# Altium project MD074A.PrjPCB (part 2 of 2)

## Sheet MD074A.SchDoc
size 431 x 279 mm; Date: Not shown in title block; ApprovedBy: Not shown in title block; CheckedBy: Not shown in title block; Author: Not shown in title block; CompanyName: Not shown in title block; Engineer: Not shown in title block; Organization: Not shown in title block; Address1: Not shown in title block; Address2: Not shown in title block; Address3: Not shown in title block; Address4: Not shown in title block; DocumentNumber: 2; Revision: Use project parameter SCH_Rev; SheetNumber: 2; SheetTotal: 3; PageSetup: Record=PageOptions¦CenterHorizontal=True¦CenterVertical=True¦PrintScale=1.00¦XCorrection=1.00¦YCorrection=1.00¦PrintKind=0¦BorderSize=5000000¦LeftOffset=0¦BottomOffset=0¦Orientation=2¦PaperLength=1000¦PaperWidth=1000¦Scale=100¦PaperSource=15¦PrintQuality=600¦MediaType=1¦DitherType=10¦PaperKind=Letter¦PrintScaleMode=1
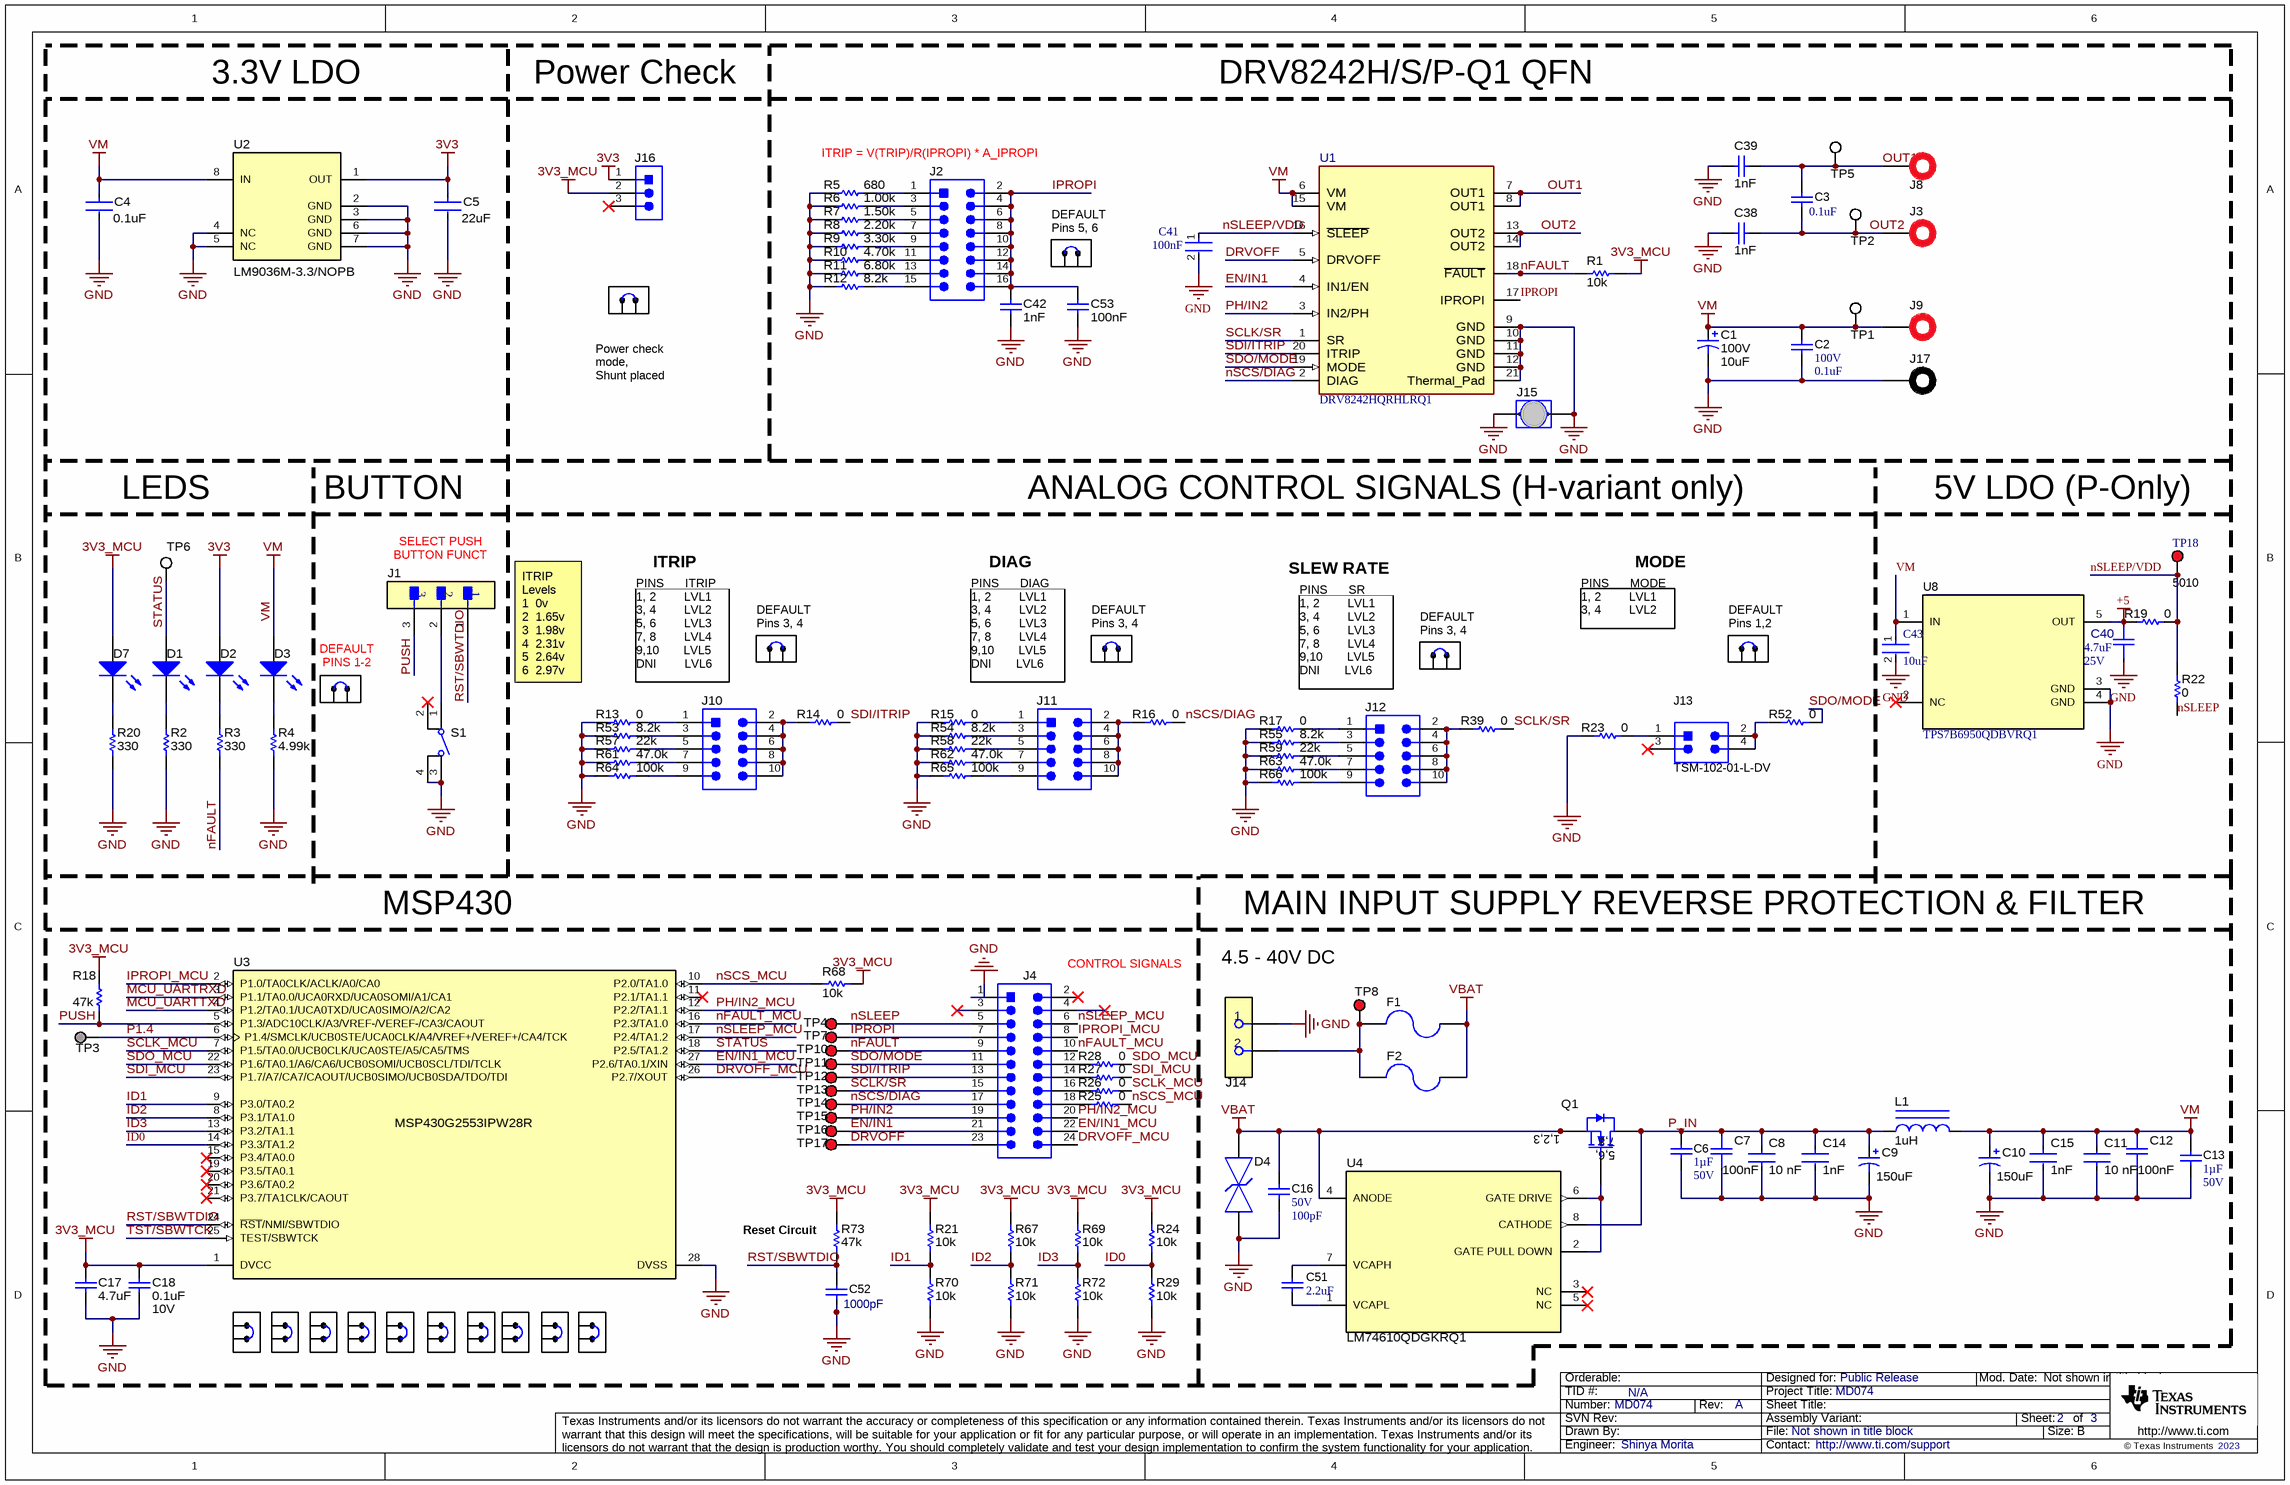
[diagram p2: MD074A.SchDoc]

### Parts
C1  VDC_V: 100V  ValueDisplayed: 10uF  [SM_RADIAL_E]  (hidden comment: EEE-2AA100UP)
C2  VDC_V: 100V  ValueDisplayed: 0.1uF  [1206_180]  (hidden comment: C3216X7R2A104K160AA)
C3  ValueDisplayed: 0.1uF  [1206_180]  (hidden comment: C3216X7R2A104K160AA)
C4  value 0.1uF  [FP-CL10-0_1-MFG]  (hidden comment: CL10B104JB8NNNC)
C5  value 22uF  [FP-CL10-IPC_A]  (hidden comment: CL10A226MQ8NUNE)
C6  Cap_F: 1µF  VDC_V: 50V  [0805_HV]  (hidden comment: 885012207103)
C7  Cap_F: 100nF  [FP-885012206095_0603-MFG]  (hidden comment: 885012206095)
C8  value 10 nF  [FP-CC0603-DA-MFG]  (hidden comment: CC0603KPX7R9BB103)
C9  ValueDisplayed: 150uF  [SM_RADIAL_G]  (hidden comment: EEE-FK1H151P)
C10  ValueDisplayed: 150uF  [SM_RADIAL_G]  (hidden comment: EEE-FK1H151P)
C11  value 10 nF  [FP-CC0603-DA-MFG]  (hidden comment: CC0603KPX7R9BB103)
C12  Cap_F: 100nF  [FP-885012206095_0603-MFG]  (hidden comment: 885012206095)
C13  Cap_F: 1µF  VDC_V: 50V  [0805_HV]  (hidden comment: 885012207103)
C14  1nF  [FP-C0603C-CF-MFG]
C15  1nF  [FP-C0603C-CF-MFG]
C16  VDC_V: 50V  ValueDisplayed: 100pF  [0805_HV]  (hidden comment: 885012007057)
C17  ValueDisplayed: 4.7uF  [0402_065L]  (hidden comment: Capacitor)
C18  ValueDisplayed: 0.1uF  VDC_V: 10V  [0603L]  (hidden comment: 885012206020)
C38  Cap_F: 1nF  [0603]  (hidden comment: CGA3E2X7R2A102K080AA)
C39  Cap_F: 1nF  [0603]  (hidden comment: CGA3E2X7R2A102K080AA)
C40  ValueDisplayed: 4.7uF  VDC_V: 25V  [FP-GRM188R61E475KE15D_0603-MFG]  (hidden comment: GRM188R61E475KE15D)
C41  Capacitance: 100nF  [FP-CGA3E-0_3-0_1-MFG]  (hidden comment: CGA3E2X7R1E104K080AA)
C42  Cap_F: 1nF  [0603]  (hidden comment: CGA3E2X7R2A102K080AA)
C43  Capacitance: 10uF  [FP-C5750-230-0_5-MFG]  (hidden comment: C5750X7S2A106M230KE)
C51  ValueDisplayed: 2.2uF  [0805_HV]  (hidden comment: C2012X5R1H225K125AB)
C52  ValueDisplayed: 1000pF  [0402]  (hidden comment: GRM155R71H102KA01D)
C53  Cap_F: 100nF  [0603]  (hidden comment: CGA3E2X7R1H104K080AA)
D1  150080VS75000  [0805_A]  (value not drawn)
D2  150080SS75000  [0805_A]  (value not drawn)
D3  150080VS75000  [0805_A]  (value not drawn)
D4  SMAJ36CA  [FP-SMAJ-CA-MFG]  (value not drawn)
D7  150080VS75000  [0805_A]  (value not drawn)
F1  0463015.ER  [Fuse_0463]  (value not drawn)
F2  0463030.ER  [Fuse_0463]  (value not drawn)
J1  PR20203VBNN  [FP-PR20203VBNN-MFG]  (value not drawn)
J2  TSM-108-01-L-DV  [Samtec_TSM-108-01-x-DV]  (value not drawn)
J3  CT3151SP-2  [CTE_CT3151SP-2]  (value not drawn)
J4  67997-224HLF  [FCI_67997-224HLF]  (value not drawn)
J8  CT3151SP-2  [CTE_CT3151SP-2]  (value not drawn)
J9  CT3151SP-2  [CTE_CT3151SP-2]  (value not drawn)
J10  TSM-105-01-L-DV-P  [Samtec_TSM-105-01-x-DV]  (value not drawn)
J11  TSM-105-01-L-DV-P  [Samtec_TSM-105-01-x-DV]  (value not drawn)
J12  TSM-105-01-L-DV-P  [Samtec_TSM-105-01-x-DV]  (value not drawn)
J13  TSM-102-01-L-DV  [Samtec_TSM-102-01-x-DV]
J14  691256610002  [FP-691256610002_HDR2-MFG]  (value not drawn)
J15  D3082-05  [Harwin_D3082-05]  (value not drawn)
J16  TSW-103-08-G-S  [Samtec_TSW-103-08-x-S]  (value not drawn)
J17  CT3151SP-0  [CTE_CT3151SP-0]  (value not drawn)
L1  ValueDisplayed: 1uH  [WE-HCC_1210]  (hidden comment: 7443320100)
Q1  CSD18513Q5A  [DQJ0008A]  (value not drawn)
R1  ValueDisplayed: 10k  [0603]  (hidden comment: RC0603JR-0710KL)
R2  ValueDisplayed: 330  [0603L]  (hidden comment: CMP-0025785-4)
R3  ValueDisplayed: 330  [0603L]  (hidden comment: CMP-0025785-4)
R4  ValueDisplayed: 4.99k  [0603L]  (hidden comment: CRCW06034K99FKEAC)
R5  ValueDisplayed: 680  [0603]  (hidden comment: RC0603FR-07680RL)
R6  ValueDisplayed: 1.00k  [0603]  (hidden comment: RC0603FR-071KL)
R7  ValueDisplayed: 1.50k  [0603]  (hidden comment: RC0603FR-071K5L)
R8  ValueDisplayed: 2.20k  [0603]  (hidden comment: RC0603FR-072K2L)
R9  ValueDisplayed: 3.30k  [0603]  (hidden comment: RC0603FR-073K3L)
R10  ValueDisplayed: 4.70k  [0603]  (hidden comment: RC0603FR-074K7L)
R11  ValueDisplayed: 6.80k  [0603]  (hidden comment: RC0603FR-076K8L)
R12  ValueDisplayed: 8.2k  [0603]  (hidden comment: CRCW06038K20JNEA)
R13  ValueDisplayed: 0  [0603]  (hidden comment: PMR03EZPJ000)
R14  ValueDisplayed: 0  [0603]  (hidden comment: PMR03EZPJ000)
R15  ValueDisplayed: 0  [0603]  (hidden comment: PMR03EZPJ000)
R16  ValueDisplayed: 0  [0603]  (hidden comment: PMR03EZPJ000)
R17  ValueDisplayed: 0  [0603]  (hidden comment: PMR03EZPJ000)
R18  ValueDisplayed: 47k  [0603]  (hidden comment: RC0603JR-0747KL)
R19  ValueDisplayed: 0  [0603]  (hidden comment: PMR03EZPJ000)
R20  ValueDisplayed: 330  [0603L]  (hidden comment: CMP-0025785-4)
R21  ValueDisplayed: 10k  [0603]  (hidden comment: RC0603JR-0710KL)
R22  ValueDisplayed: 0  [0603]  (hidden comment: PMR03EZPJ000)
R23  ValueDisplayed: 0  [0603]  (hidden comment: PMR03EZPJ000)
R24  ValueDisplayed: 10k  [0603]  (hidden comment: RC0603JR-0710KL)
R25  value 0  [RESC1609X55X30NL10T20]  (hidden comment: CRCW06030000Z0EAHP)
R26  value 0  [RESC1609X55X30NL10T20]  (hidden comment: CRCW06030000Z0EAHP)
R27  value 0  [RESC1609X55X30NL10T20]  (hidden comment: CRCW06030000Z0EAHP)
R28  value 0  [RESC1609X55X30NL10T20]  (hidden comment: CRCW06030000Z0EAHP)
R29  ValueDisplayed: 10k  [0603]  (hidden comment: RC0603JR-0710KL)
R39  ValueDisplayed: 0  [0603]  (hidden comment: PMR03EZPJ000)
R52  ValueDisplayed: 0  [0603]  (hidden comment: PMR03EZPJ000)
R53  ValueDisplayed: 8.2k  [0603]  (hidden comment: CRCW06038K20JNEA)
R54  ValueDisplayed: 8.2k  [0603]  (hidden comment: CRCW06038K20JNEA)
R55  ValueDisplayed: 8.2k  [0603]  (hidden comment: CRCW06038K20JNEA)
R57  ValueDisplayed: 22k  [0603]  (hidden comment: CRCW060322K0JNEA)
R58  ValueDisplayed: 22k  [0603]  (hidden comment: CRCW060322K0JNEA)
R59  ValueDisplayed: 22k  [0603]  (hidden comment: CRCW060322K0JNEA)
R61  ValueDisplayed: 47.0k  [0603]  (hidden comment: CRCW060347K0FKEA)
R62  ValueDisplayed: 47.0k  [0603]  (hidden comment: CRCW060347K0FKEA)
R63  ValueDisplayed: 47.0k  [0603]  (hidden comment: CRCW060347K0FKEA)
R64  ValueDisplayed: 100k  [0603]  (hidden comment: CRCW0603100KDHEAP)
R65  ValueDisplayed: 100k  [0603]  (hidden comment: CRCW0603100KDHEAP)
R66  ValueDisplayed: 100k  [0603]  (hidden comment: CRCW0603100KDHEAP)
R67  ValueDisplayed: 10k  [0603]  (hidden comment: RC0603JR-0710KL)
R68  ValueDisplayed: 10k  [0603]  (hidden comment: RC0603JR-0710KL)
R69  ValueDisplayed: 10k  [0603]  (hidden comment: RC0603JR-0710KL)
R70  ValueDisplayed: 10k  [0603]  (hidden comment: RC0603JR-0710KL)
R71  ValueDisplayed: 10k  [0603]  (hidden comment: RC0603JR-0710KL)
R72  ValueDisplayed: 10k  [0603]  (hidden comment: RC0603JR-0710KL)
R73  ValueDisplayed: 47k  [0402]  (hidden comment: CRCW040247K0JNED)
S1  FSM4JSMA  [SW_FSM4JSMA]  (value not drawn)
SH-J1  60900213421  [Wurth_60900213421]  (value not drawn)
SH-J2  60900213421  [Wurth_60900213421]  (value not drawn)
SH-J3  60900213421  [Wurth_60900213421]  (value not drawn)
SH-J4  60900213421  [Wurth_60900213421]  (value not drawn)
SH-J5  60900213421  [Wurth_60900213421]  (value not drawn)
SH-J6  60900213421  [Wurth_60900213421]  (value not drawn)
SH-J7  60900213421  [Wurth_60900213421]  (value not drawn)
SH-J8  60900213421  [Wurth_60900213421]  (value not drawn)
SH-J9  60900213421  [Wurth_60900213421]  (value not drawn)
SH-J10  60900213421  [Wurth_60900213421]  (value not drawn)
SH-J11  60900213421  [Wurth_60900213421]  (value not drawn)
SH-J12  60900213421  [Wurth_60900213421]  (value not drawn)
SH-J13  60900213421  [Wurth_60900213421]  (value not drawn)
SH-J14  60900213421  [Wurth_60900213421]  (value not drawn)
SH-J15  60900213421  [Wurth_60900213421]  (value not drawn)
SH-J16  60900213421  [Wurth_60900213421]  (value not drawn)
SH-J17  60900213421  [Wurth_60900213421]  (value not drawn)
TP1  5015  [Testpoint_Keystone_Miniature]  (value not drawn)
TP2  5015  [Testpoint_Keystone_Miniature]  (value not drawn)
TP3  TP_H0.45P0.75  [TP_H045P075]  (value not drawn)  (no BOM)
TP4  5010  [Keystone5010]  (value not drawn)
TP5  5015  [Testpoint_Keystone_Miniature]  (value not drawn)
TP6  5015  [Testpoint_Keystone_Miniature]  (value not drawn)
TP7  5010  [Keystone5010]  (value not drawn)
TP8  5010  [Keystone5010]  (value not drawn)
TP10  5010  [Keystone5010]  (value not drawn)
TP11  5010  [Keystone5010]  (value not drawn)
TP12  5010  [Keystone5010]  (value not drawn)
TP13  5010  [Keystone5010]  (value not drawn)
TP14  5010  [Keystone5010]  (value not drawn)
TP15  5010  [Keystone5010]  (value not drawn)
TP16  5010  [Keystone5010]  (value not drawn)
TP17  5010  [Keystone5010]  (value not drawn)
TP18  5010  [Keystone5010]
U1  DRV8242HQRHLRQ1  [RHL0020B-MFG]
U2  LM9036M-3.3/NOPB  [D0008A_N]
U3  MSP430G2553IPW28R  [PW0028A_N]
U4  LM74610QDGKRQ1  [DGK0008A_N]
U8  TPS7B6950QDBVRQ1  [DBV0005A_N]

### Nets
3V3: C5.1 D2.2(A) J16.1 U2.1(OUT)
3V3_MCU: C17.1 C18.1 D7.2(A) J16.2 R1.2 R18.2 R21.1 R24.1 R67.1 R68.1 R69.1 R73.2 U3.1(DVCC)
+5: C40.2 R19.2 U8.5(OUT)
GND: C1.2(-) C2.2 C4.2 C5.2 C6.1 C7.1 C8.1 C9.2(-) C10.2(-) C11.1 C12.1 C13.1 C14.2 C15.2 C16.2 C17.2 C18.2 C38.1 C39.1 C40.1 C41.2 C42.1 C43.2 C52.2 C53.2 D4.1 J4.1 J14.1 J15.1 J15.2 J17.1 R2.1 R4.1 R5.1 R6.1 R7.1 R8.1 R9.1 R10.1 R11.1 R12.1 R13.2 R15.2 R17.2 R20.1 R23.2 R29.2 R53.1 R54.1 R55.1 R57.1 R58.1 R59.1 R61.1 R62.1 R63.1 R64.1 R65.1 R66.1 R70.2 R71.2 R72.2 S1.3 S1.4 U1.9(GND) U1.10(GND) U1.11(GND) U1.12(GND) U1.21(Thermal_Pad) U2.2(GND) U2.3(GND) U2.4(NC) U2.5(NC) U2.6(GND) U2.7(GND) U3.28(DVSS) U8.3(GND) U8.4(GND)
VBAT: C16.1 D4.2 F1.1 F2.1 Q1.1(S) Q1.2(S) Q1.3(S) U4.4(ANODE)
VM: C1.1(+) C2.1 C4.1 C10.1(+) C11.2 C12.2 C13.2 C15.1 C43.1 D3.2(A) J9.1 L1.2 TP1.1 U1.6(VM) U1.15(VM) U2.8(IN) U8.1(IN)
DRVOFF: J4.23 TP17.1 U1.5(DRVOFF)
DRVOFF_MCU: J4.24 U3.26(P2.7/XOUT)
EN/IN1: J4.21 TP16.1 U1.4(IN1/EN)
EN/IN1_MCU: J4.22 U3.27(P2.6/TA0.1/XIN)
ID0: R24.2 R29.1 U3.14(P3.3/TA1.2)
ID1: R21.2 R70.1 U3.9(P3.0/TA0.2)
ID2: R67.2 R71.1 U3.8(P3.1/TA1.0)
ID3: R69.2 R72.1 U3.13(P3.2/TA1.1)
IPROPI: C42.2 C53.1 J2.2 J2.4 J2.6 J2.8 J2.10 J2.12 J2.14 J2.16 J4.7 TP7.1 U1.17(IPROPI)
IPROPI_MCU: J4.8 U3.2(P1.0/TA0CLK/ACLK/A0/CA0)
MCU_UARTRXD: U3.3(P1.1/TA0.0/UCA0RXD/UCA0SOMI/A1/CA1)
MCU_UARTTXD: U3.4(P1.2/TA0.1/UCA0TXD/UCA0SIMO/A2/CA2)
nFAULT: J4.9 R1.1 R3.1 TP10.1 U1.18(~{FAULT})
nFAULT_MCU: J4.10 U3.16(P2.3/TA1.0)
nSCS/DIAG: J4.17 R16.1 TP14.1 U1.2(DIAG)
nSCS_MCU: R25.2 R68.2 U3.10(P2.0/TA1.0)
nSLEEP: J4.5 R22.2 TP4.1
nSLEEP/VDD: C41.1 R19.1 R22.1 TP18.1 U1.16(~{SLEEP})
nSLEEP_MCU: J4.6 U3.17(P2.4/TA1.2)
OUT1: C3.1 C39.2 J8.1 TP5.1 U1.7(OUT1) U1.8(OUT1)
OUT2: C3.2 C38.2 J3.1 TP2.1 U1.13(OUT2) U1.14(OUT2)
P1.4: TP3.1 U3.6(P1.4/SMCLK/UCB0STE/UCA0CLK/A4/VREF+/VEREF+/CA4/TCK)
P_IN: C6.2 C7.2 C8.2 C9.1(+) C14.1 L1.1 Q1.5(D) Q1.6(D) Q1.7(D) Q1.8(D) Q1.9(D) U4.8(CATHODE)
PH/IN2: J4.19 TP15.1 U1.3(IN2/PH)
PH/IN2_MCU: J4.20 U3.12(P2.2/TA1.1)
PUSH: J1.3 R18.1 U3.5(P1.3/ADC10CLK/A3/VREF-/VEREF-/CA3/CAOUT)
RST/SBWTDIO: C52.1 J1.1 R73.1 U3.24(~{RST}/NMI/SBWTDIO)
SCLK/SR: J4.15 R39.1 TP13.1 U1.1(SR)
SCLK_MCU: R26.2 U3.7(P1.5/TA0.0/UCB0CLK/UCA0STE/A5/CA5/TMS)
SDI/ITRIP: J4.13 R14.1 TP12.1 U1.20(ITRIP)
SDI_MCU: R27.2 U3.23(P1.7/A7/CA7/CAOUT/UCB0SIMO/UCB0SDA/TDO/TDI)
SDO/MODE: J4.11 R52.1 TP11.1 U1.19(MODE)
SDO_MCU: R28.2 U3.22(P1.6/TA0.1/A6/CA6/UCB0SOMI/UCB0SCL/TDI/TCLK)
STATUS: D1.2(A) TP6.1 U3.18(P2.5/TA1.2)
TST/SBWTCK: U3.25(TEST/SBWTCK)
NetC51_1: C51.1 U4.7(VCAPH)
NetC51_2: C51.2 U4.1(VCAPL)
NetD1_1: D1.1(K) R2.2
NetD2_1: D2.1(K) R3.2
NetD3_1: D3.1(K) R4.2
NetD7_1: D7.1(K) R20.2
NetF1_2: F1.2 F2.2 J14.2 TP8.1
NetJ1_2: J1.2 S1.1
NetJ2_1: J2.1 R5.2
NetJ2_3: J2.3 R6.2
NetJ2_5: J2.5 R7.2
NetJ2_7: J2.7 R8.2
NetJ2_9: J2.9 R9.2
NetJ2_11: J2.11 R10.2
NetJ2_13: J2.13 R11.2
NetJ2_15: J2.15 R12.2
NetJ4_12: J4.12 R28.1
NetJ4_14: J4.14 R27.1
NetJ4_16: J4.16 R26.1
NetJ4_18: J4.18 R25.1
NetJ10_1: J10.1 R13.1
NetJ10_2: J10.2 J10.4 J10.6 J10.8 J10.10 R14.2
NetJ10_3: J10.3 R53.2
NetJ10_5: J10.5 R57.2
NetJ10_7: J10.7 R61.2
NetJ10_9: J10.9 R64.2
NetJ11_1: J11.1 R15.1
NetJ11_2: J11.2 J11.4 J11.6 J11.8 J11.10 R16.2
NetJ11_3: J11.3 R54.2
NetJ11_5: J11.5 R58.2
NetJ11_7: J11.7 R62.2
NetJ11_9: J11.9 R65.2
NetJ12_1: J12.1 R17.1
NetJ12_2: J12.2 J12.4 J12.6 J12.8 J12.10 R39.2
NetJ12_3: J12.3 R55.2
NetJ12_5: J12.5 R59.2
NetJ12_7: J12.7 R63.2
NetJ12_9: J12.9 R66.2
NetJ13_1: J13.1 R23.1
NetJ13_2: J13.2 J13.4 R52.2
NetQ1_4: Q1.4(G) U4.2(GATE_PULL_DOWN) U4.6(GATE_DRIVE)

Not connected (* = marked no-connect by the designer): J4 2* 3* 4*; J13 3*; J16 3*; S1 2*; U3 11(P2.1/TA1.1)* 15(P3.4/TA0.0)* 19(P3.5/TA0.1)* 20(P3.6/TA0.2)* 21(P3.7/TA1CLK/CAOUT)*; U4 3(NC)* 5(NC)*; U8 2(NC)*

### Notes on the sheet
- 3.3V LDO
- Power Check
- DRV8242H/S/P-Q1 QFN
- ITRIP = V(TRIP)/R(IPROPI) * A_IPROPI
- (near SH-J5) DEFAULT
  Pins 5, 6
- (near SH-J7) Power check mode,
  Shunt placed
- LEDS
- BUTTON
- ANALOG CONTROL SIGNALS (H-variant only)
- 5V LDO (P-Only)
- SELECT PUSH
- (near J1) BUTTON FUNCT
- ITRIP
- DIAG
- SLEW RATE
- MODE
- PINS      ITRIP
- (near SH-J2) DEFAULT
  Pins 3, 4
- PINS      DIAG
- (near SH-J13) DEFAULT
  Pins 3, 4
- PINS      SR
- (near SH-J16) DEFAULT
  Pins 3, 4
- PINS      MODE
- 1, 2        LVL1
  3, 4        LVL2
- (near SH-J14) DEFAULT
  Pins 1,2
- DEFAULT
- (near SH-J1) PINS 1-2
- ITRIP Levels
  1  0v
  2  1.65v
  3  1.98v
  4  2.31v
  5  2.64v
  6  2.97v
- 1, 2        LVL1
  3, 4        LVL2
  5, 6        LVL3
  7, 8        LVL4
  9,10       LVL5
  DNI        LVL6
- 1, 2        LVL1
  3, 4        LVL2
  5, 6        LVL3
  7, 8        LVL4
  9,10       LVL5
  DNI       LVL6
- MSP430
- MAIN INPUT SUPPLY REVERSE PROTECTION & FILTER
- (near J4) CONTROL SIGNALS
- 4.5 - 40V DC
- (near R73) Reset Circuit

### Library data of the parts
C1 = CMP-0011164-2: CAP, AL, 10 uF, 100 V, +/- 20%, AEC-Q200 Grade 3, SMD; Manufacturer: Panasonic; Alternate Manufacturer: Wurth Elektronik; Alternate PartNumber: 865080845005; TaMin_C: -40°C; Polarized: Y; SizeAreaWB_mm2: 118.45; Value1: Unknown; U/M: EA; Value: 10uF; TaMax_C: 85°C; SizeZ_mm: 6.2; SizeX_mm: 9.5; SizeY_mm: 8.3; Cap_Case: 8.0x6.0mm; SizeArea_mm2: 78.85; CompType: Capacitor; Cap_F: 10µF; IRMS_A: 50mA; AEC Grade: 3; AEC Category: Q200
C2 = CMP-0008709-2: CAP, CERM, 0.1 uF, 100 V, +/- 10%, X7R, 1206; Manufacturer: TDK; TaMin_C: -55°C; ESR_ohm: 30.343m; Polarized: N; SizeAreaWB_mm2: 10.92; Value1: 0.030343 ohm; U/M: EA; Value: 0.1uF; TaMax_C: 125°C; SizeZ_mm: 1.8; SizeX_mm: 3.2; SizeY_mm: 1.6; SizeArea_mm2: 5.12; Cap_F: 100nF; IRMS_A: 1.338A; AEC Category: Q200
C3 = CMP-0008709-2: CAP, CERM, 0.1 uF, 100 V, +/- 10%, X7R, 1206; Manufacturer: TDK; TaMin_C: -55°C; ESR_ohm: 30.343m; Polarized: N; SizeAreaWB_mm2: 10.92; Value1: 0.030343 ohm; U/M: EA; Value: 0.1uF; TaMax_C: 125°C; SizeZ_mm: 1.8; SizeX_mm: 3.2; SizeY_mm: 1.6; Value2: 100V; SizeArea_mm2: 5.12; Cap_F: 100nF; IRMS_A: 1.338A; AEC Category: Q200
C4 = CMP-13271-000011-1: CAP CER 0.1UF 50V X7R 0603; Manufacturer: Samsung Electro-Mechanics America, Inc; Alternative PartNumber: 885012206095; Alternative Manufacturer: Wurth Elektronik; Material: Ceramic; Temperature Coefficient: 15%; Tolerance: 5%; Capacitance: 100nF
C5 = CMP-13271-003053-1: Cap Ceramic 22uF 6.3V X5R ±20% Pad SMD 0603 +85°C T/R; Manufacturer: Samsung
C6 C13 = CMP-0007696-2: CAP, CERM, 1 uF, 50 V, +/- 10%, X7R, 0805; Manufacturer: Wurth Elektronik; TaMin_C: -55°C; Polarized: N; SizeAreaWB_mm2: 6.75; Value1: Unknown; U/M: EA; Value: 1uF; TaMax_C: 125°C; SizeZ_mm: 1.45; SizeX_mm: 2; SizeY_mm: 1.25; Cap_Case: 0805; SizeArea_mm2: 2.5; AEC Category: Q200
C7 C12 = CMP-0097346-1: 0.1 µF ±10% 50V Ceramic Capacitor X7R 0603 (1608 Metric); Manufacturer: Wurth; TempCo: 15%; Value: 100nF; AEC Qualified: No; SizeZ_mm: 0.87mm
C8 C11 = CMP-1035-02321-3: CAP CER 10000PF 50V X7R 0603; Manufacturer: YAGEO; Alternate PartNumber: 885012206089; Alternate Manufacturer: Wurth Elektronik; Tolerance: 0.1; Material: Ceramic; Temperature Coefficient: 15%
C9 C10 = CMP-0011178-2: CAP, AL, 150 uF, 50 V, +/- 20%, 0.18 ohm, AEC-Q200 Grade 2, SMD; Manufacturer: Panasonic; Alternate Manufacturer: Wurth Elektronik; Alternate PartNumber: 865080657017; TaMin_C: -55°C; ESR_ohm: 0.18; Polarized: Y; SizeAreaWB_mm2: 172.2; U/M: EA; Value: 150uF; TaMax_C: 105°C; SizeZ_mm: 10.2; SizeX_mm: 12; SizeY_mm: 10.3; Cap_Case: G; Value2: 50V; SizeArea_mm2: 123.6; CompType: Capacitor; Cap_F: 150µF; IRMS_A: 670mA; AEC Grade: 2; AEC Category: Q200
C14 C15 = CMP-03020-030804-1: CAP CER 1000PF 50V X7R 0603; PartNumber: C0603C102J5RACAUTO; Manufacturer: KEMET; Alternate PartNumber: 885012206083; Alternate Manufacturer: Wurth Elektronik; Material: Ceramic; Value: 1,000 pF; Temperature Coefficient: 30ppm/°C; Automotive Grade: Grade 1; Tolerance: 0.05
C16 = CMP-0081453-1: CAP, CERM, 100 pF, 50 V,+/- 5%, C0G/NP0, 0805; Manufacturer: Wurth Elektronik; TaMin_C: -55°C; Polarized: N; SizeAreaWB_mm2: 6.75; U/M: EA; Value: 100pF; TaMax_C: 125°C; SizeZ_mm: 1.45; SizeX_mm: 2; SizeY_mm: 1.25; Cap_Case: 0805; SizeArea_mm2: 2.5; AEC Category: Q200
C17 = CMP-0006268-2: CAP, CERM, 4.7 uF, 10 V, +/- 10%, X5R, 0402; PartNumber: C1005X5R1A475K050BC; Manufacturer: TDK; Alternate PartNumber: 885012106012; Alternate Manufacturer: Wurth Elektronik; Polarized: N; Value: 4.7uF; U/M: EA; Cap_F: 4.7µF; ESR_ohm: 3.417m; Value1: 0.003417 ohm; VDC_V: 10V; IRMS_A: 2.7063A; TaMin_C: -55°C; TaMax_C: 85°C; Cap_Case: 0402_065; AEC Category: Q200; SizeArea_mm2: 0.5; SizeAreaWB_mm2: 3; SizeX_mm: 1; SizeZ_mm: 0.65
C18 = CMP-0064931-4: CAP, CERM, 0.1 uF, 10 V,+/- 10%, X7R, 0603; Manufacturer: Wurth Elektronik; Polarized: N; CompType: Capacitor; Value: 0.1uF; U/M: EA; Cap_F: 100nF; Value1: Unknown; TaMin_C: -55°C; TaMax_C: 125°C; Cap_Case: 0603; AEC Category: Q200; SizeArea_mm2: 1.28; SizeAreaWB_mm2: 4.68; SizeX_mm: 1.6; SizeY_mm: 0.8; SizeZ_mm: 1
C38 C39 C42 = CMP-0007081-4: CAP, CERM, 1000 pF, 100 V, +/- 10%, X7R, AEC-Q200 Grade 1, 0603; Manufacturer: TDK; Alternate Manufacturer: Wurth Elektronik; Alternate PartNumber: 885012006085; TaMin_C: -55°C; ESR_ohm: 1.97137; Polarized: N; SizeAreaWB_mm2: 4.68; Value1: 1.97137 ohm; U/M: EA; Value: 1000pF; TaMax_C: 125°C; SizeZ_mm: 1; SizeX_mm: 1.6; SizeY_mm: 0.8; Value2: 100V; SizeArea_mm2: 1.28; AEC Qualified: Y; IRMS_A: 305.705mA; AEC Category: Q200
C40 = CMP-0091702-1: 4.7µF ±10% 25V Ceramic Capacitor X5R 0603 (1608 Metric); Manufacturer: Murata; AEC Qualified: No; SizeZ_mm: 1mm; TempCo: 15%
C41 = CMP-08246-002186-1: Cap Ceramic 100nF 25V X7R 10% Pad SMD 0603 +125°C Automotive T/R
C43 = CMP-08246-007260-1: CAP CER 10UF 100V X7S 2220; Tolerance: 20%
C51 = CMP-0007836-2: CAP, CERM, 2.2 uF, 50 V, +/- 10%, X5R, 0805; Manufacturer: TDK; TaMin_C: -55°C; ESR_ohm: 3.66m; Polarized: N; SizeAreaWB_mm2: 6.75; Value1: 0.00366 ohm; U/M: EA; Value: 2.2uF; TaMax_C: 85°C; SizeZ_mm: 1.45; SizeX_mm: 2; SizeY_mm: 1.25; Cap_Case: 0805; Value2: 50V; SizeArea_mm2: 2.5; Cap_F: 2.2µF; IRMS_A: 3.4121A; AEC Category: Q200
C52 = CMP-0006673-2: CAP, CERM, 1000 pF, 50 V, +/- 10%, X7R, 0402; Manufacturer: MuRata; Alternate Manufacturer: Wurth Elektronik; Alternate PartNumber: 885012205061; TaMin_C: -55°C; Polarized: N; SizeAreaWB_mm2: 3; Value1: Unknown; U/M: EA; Value: 1000pF; TaMax_C: 125°C; SizeZ_mm: 0.6; SizeX_mm: 1; SizeY_mm: 0.5; Value2: 50V; Cap_F: 1nF; AEC Category: Q200
C53 = CMP-0007078-4: CAP, CERM, 0.1 uF, 50 V, +/- 10%, X7R, AEC-Q200 Grade 1, 0603; Manufacturer: TDK; Alternate Manufacturer: Wurth Elektronik; Alternate PartNumber: 885012206095; TaMin_C: -55°C; ESR_ohm: 29.6m; Polarized: N; SizeAreaWB_mm2: 4.68; Value1: 0.0296 ohm; U/M: EA; Value: 0.1uF; TaMax_C: 125°C; SizeZ_mm: 1; SizeX_mm: 1.6; SizeY_mm: 0.8; Value2: 50V; SizeArea_mm2: 1.28; AEC Qualified: Y; IRMS_A: 971.99mA; AEC Category: Q200
D1 D3 D7 = CMP-1426-00009-1: SMD mono-color Chip LED, WL-SMCW, Bright Green; Manufacturer: Wuerth Elektronik
D2 = CMP-1426-00010-1: SMD mono-color Chip LED, WL-SMCW, Super Red; Manufacturer: Wuerth Elektronik
D4 = CMP-08607-000009-1: TVS DIODE 36V 58.1V DO214AC; Manufacturer: Littelfuse Inc; Peak Pulse Power: 400W; Max Junction Temp: +150°C; Direction: Bidirectional; Peak Pulse Current: 6.9A; Number Of Channels: 1; Breakdown Voltage: 40V
F1 = CMP-0081016-1: Fuse, 15 A, 250 VAC, 100 VDC, SMD; Manufacturer: Littelfuse; VAC_V: 250V; SizeAreaWB_mm2: 61.952; Rtyp_Ohm: 4.7m; SizeArea_mm2: 31.512; MeltingTyp: 142; Irating_A: 15A; SizeZ_mm: 3.12; VDC_V: 100V; SizeX_mm: 10.1; Interrupt_AC: 100A; Interrupt_DC: 50A; Fuse Speed: Fast; Fuse Technology: Board Mount; TaMax_C: 125°C; TaMin_C: -55°C
F2 = CMP-0077200-3: Fuse, 30 A, 250 VAC, 100 VDC, SMD; Manufacturer: Littelfuse; VAC_V: 250V; SizeAreaWB_mm2: 61.952; Rtyp_Ohm: 1.93m; SizeArea_mm2: 31.512; MeltingTyp: 916; Irating_A: 30A; SizeZ_mm: 3.12; VDC_V: 100V; SizeX_mm: 10.1; Interrupt_AC: 100A; Interrupt_DC: 50A; Fuse Speed: Fast; Fuse Technology: Board Mount; TaMax_C: 125°C; TaMin_C: -55°C
J1 = CMP-77940-000002-1: CONN HEADER VERT 3POS 2.54MM; Manufacturer: Metz Connect; Alternative PartNumber: 61900311121; Alternative Manufacturer: Wurth Elektronik; Conn Orientation: Straight; Current Rating: 3A; Number Of Contacts: 3; Conn Gender: Male
J2 = CMP-0075595-1: Header, 2.54mm, 8x2, Gold, SMT; Manufacturer: Samtec; Alternate Manufacturer: Wurth Elektronik; Alternate PartNumber: 61001621121; Pitch_mm: 2.54; Gender: Male; Cert_CSA: Y; Current_A: 4.9A; Voltage_V: 475V; CT: False; Shrouded: N; Row_Count: 2; CNHeader: True
J3 J8 J9 = CMP-0055418-2: Banana Jack Insul Nylon Red, R/A, TH; Manufacturer: Cal Test Electronics; CNHeader: FALSE; Current_A: 25A; Gender: Female; Voltage_V: 1kV; Row_Count: 1; ContactFinish: Nickel; CT: TRUE; Cert_UL: Y
J4 = CMP-0085938-1: Header, 2.54mm, 12x2, Gold, TH; Manufacturer: FCI; Alternate Manufacturer: Wurth Elektronik; Alternate PartNumber: 61302421121; Current_A: 5A; Shrouded: N; Gender: Male; Voltage_V: 1.5kV; Row_Count: 2; Pitch_mm: 2.54; Cert_UL: Y
J10-J12 = CMP-0055598-2: Header, 2.54mm, 5x2, Gold, SMT; Manufacturer: Samtec; Alternate Manufacturer: Wurth Elektronik; Alternate PartNumber: 61031021121; Current_A: 5.4A; Green_Lifecycle: Active; Shrouded: N; Gender: Male; Cert_CSA: Y; Green_REACh: Passed; Voltage_V: 475V; Row_Count: 2; RowSpacing_mm: 2.54
J13 = CMP-0055559-1: Header, 2.54mm, 2x2, Gold, SMT; Manufacturer: Samtec; Pitch_mm: 2.54; Gender: Male; Cert_UL: Y; Voltage_V: 475V; Shrouded: N; Row_Count: 2; CNHeader: TRUE; CT: FALSE
J14 = CMP-0086764-1: Manufacturer: Wurth; Current_A: 57A; Voltage_V: 750V; ContactFinish: Zinc; Row_Count: 1
J15 = CMP-0075110-1: 1mm Uninsulated Shorting Plug, 10.16mm spacing, TH; Manufacturer: Harwin; CNHeader: False; Green_Lifecycle: Active; Green_REACh: Passed; CompType: Jumper Wire
J16 = CMP-0079327-1: Header, 2.54mm, 3x1, Gold, TH; Alternate Manufacturer: Wurth Elektronik; Manufacturer: Samtec; Alternate PartNumber: 61300311121; Cert_UL: Y; Row_Count: 1; Pitch_mm: 2.54; Gender: Male; Shrouded: N
J17 = CMP-0055417-1: Banana Jack Insul Nylon Black, R/A, TH; Manufacturer: Cal Test Electronics; CNHeader: FALSE; Current_A: 25A; Gender: Female; Voltage_V: 1kV; Row_Count: 1; ContactFinish: Nickel; CT: TRUE; Cert_UL: Y
L1 = CMP-0063986-1: Inductor, Shielded Drum Core, Ferrite, 1 uH, 24 A, 0.0012 ohm, SMD; Manufacturer: Wurth Elektronik; Isat: 32A @ 30% inductance drop; Irms: 24A @ 50C rise; Green_Lifecycle: Active; SizeAreaWB_mm2: 188.94; DCR_ohm: 1.2m; Green_REACh: Passed; Value: 1uH; Imax_A: 24A; SizeZ_mm: 10; SizeX_mm: 12.1; SizeY_mm: 11.4; SizeArea_mm2: 137.94; Ind_H: 1µH; AEC Category: Q200
Q1 = CMP-0000714-1: MOSFET, N-CH, 40 V, 100 A, DQJ0008A (VSONP-8); Alternate Manufacturer: None; Manufacturer: Texas Instruments; SizeZ_mm: 1.1; ChType: N; Value2: 47 nC; Value1: 0.004; VdsMax_V: 40V; SizeX_mm: 6; SizeAreaWB_mm2: 55.2; SizeY_mm: 4.9; Vgs_V: 20V; QgTyp_nC: 47; Value: 40V; Rdson45_ohm: 4.1m; SizeArea_mm2: 29.4; AEC Category: Q101; IdsMax_A: 100A; U/M: EA
R1 R68 = CMP-0025886-3: RES, 10 k, 5%, 0.1 W, 0603; Manufacturer: Yageo America; Power_W: 100mW; TempCo: 100 ppm/C; Value_Code: 10k0; U/M: EA; Value: 10k; EIA_Code: E24; SizeX_mm: 1.6; SizeY_mm: 0.8; SizeZ_mm: 1; Value2: 0.1W; SizeArea_mm2: 1.28; VDC_V: 50V; AEC Category: Q200
R2 R3 R20 = CMP-0025785-4: RES, 330, 5%, 0.1 W, AEC-Q200 Grade 0, 0603; PartNumber: CRCW0603330RJNEA; Manufacturer: Vishay-Dale; CompType: Resistor; Value: 330; Value_Code: 330R; Power_W: 100mW; Value2: 0.1W; VDC_V: 75V; TempCo: 200 ppm/C; EIA_Code: E24; AEC Category: Q200; AEC Qualified: Y; AEC Grade: 0; SizeX_mm: 1.6; SizeY_mm: 0.8; SizeZ_mm: 1; SizeArea_mm2: 1.28
R4 = CMP-0082533-1: RES, 4.99 k, 1%, 0.1 W, 0603; Manufacturer: Vishay-Dale; CompType: Resistor; Value: 4.99k; Value_Code: 4k99; Power_W: 100mW; Value2: 0.1W; VDC_V: 75V; TempCo: 100 ppm/C; EIA_Code: E96; AEC Category: Q200; AEC Qualified: N; SizeAreaWB_mm2: 4.68; SizeX_mm: 1.6; SizeY_mm: 0.8; SizeZ_mm: 1; SizeArea_mm2: 1.28
R5 = CMP-0023235-5: RES, 680, 1%, 0.1 W, 0603; Manufacturer: Yageo; Power_W: 100mW; TempCo: 100 ppm/C; Value_Code: 680R; Value: 680; SizeX_mm: 1.6; SizeY_mm: 0.8; SizeZ_mm: 1; Value2: 0.1W; SizeArea_mm2: 1.28; AEC Qualified: N; VDC_V: 75V; AEC Category: Q200; SizeAreaWB_mm2: 4.68
R6 = CMP-0022895-5: RES, 1.00 k, 1%, 0.1 W, 0603; Manufacturer: Yageo; Power_W: 100mW; TempCo: 100 ppm/C; Value_Code: 1k00; Value: 1.00k; EIA_Code: E96; Res_ohm: 1k; SizeX_mm: 1.6; SizeY_mm: 0.8; SizeZ_mm: 1; Value2: 0.1W; SizeArea_mm2: 1.28; AEC Qualified: N; VDC_V: 75V; AEC Category: Q200; SizeAreaWB_mm2: 4.68
R7 = CMP-0022883-5: RES, 1.50 k, 1%, 0.1 W, 0603; Manufacturer: Yageo; Power_W: 100mW; TempCo: 100 ppm/C; Value_Code: 1k50; Value: 1.50k; EIA_Code: E96; Res_ohm: 1.5k; SizeX_mm: 1.6; SizeY_mm: 0.8; SizeZ_mm: 1; Value2: 0.1W; SizeArea_mm2: 1.28; AEC Qualified: N; VDC_V: 75V; AEC Category: Q200; SizeAreaWB_mm2: 4.68
R8 = CMP-0022986-5: RES, 2.20 k, 1%, 0.1 W, 0603; Manufacturer: Yageo; Power_W: 100mW; TempCo: 100 ppm/C; Value_Code: 2k20; Value: 2.20k; Res_ohm: 2.2k; SizeX_mm: 1.6; SizeY_mm: 0.8; SizeZ_mm: 1; Value2: 0.1W; SizeArea_mm2: 1.28; AEC Qualified: N; VDC_V: 75V; AEC Category: Q200; SizeAreaWB_mm2: 4.68
R9 = CMP-0023081-5: RES, 3.30 k, 1%, 0.1 W, 0603; Manufacturer: Yageo; Power_W: 100mW; TempCo: 100 ppm/C; Value_Code: 3k30; Value: 3.30k; Res_ohm: 3.3k; SizeX_mm: 1.6; SizeY_mm: 0.8; SizeZ_mm: 1; Value2: 0.1W; SizeArea_mm2: 1.28; AEC Qualified: N; VDC_V: 75V; AEC Category: Q200; SizeAreaWB_mm2: 4.68
R10 = CMP-0023153-5: RES, 4.70 k, 1%, 0.1 W, 0603; Manufacturer: Yageo; Power_W: 100mW; TempCo: 100 ppm/C; Value_Code: 4k70; Value: 4.70k; Res_ohm: 4.7k; SizeX_mm: 1.6; SizeY_mm: 0.8; SizeZ_mm: 1; Value2: 0.1W; SizeArea_mm2: 1.28; AEC Qualified: N; VDC_V: 75V; AEC Category: Q200; SizeAreaWB_mm2: 4.68
R11 = CMP-0023253-5: RES, 6.80 k, 1%, 0.1 W, 0603; Manufacturer: Yageo; Power_W: 100mW; TempCo: 100 ppm/C; Value_Code: 6k80; Value: 6.80k; Res_ohm: 6.8k; SizeX_mm: 1.6; SizeY_mm: 0.8; SizeZ_mm: 1; Value2: 0.1W; SizeArea_mm2: 1.28; AEC Qualified: N; VDC_V: 75V; AEC Category: Q200; SizeAreaWB_mm2: 4.68
R12 R53-R55 = CMP-0025862-3: RES, 8.2 k, 5%, 0.1 W, 0603; Manufacturer: Vishay-Dale; Power_W: 100mW; TempCo: 200 ppm/C; Value_Code: 8k20; U/M: EA; Value: 8.2k; EIA_Code: E24; SizeX_mm: 1.6; SizeY_mm: 0.8; SizeZ_mm: 1; Value2: 0.1W; SizeArea_mm2: 1.28; VDC_V: 75V; AEC Category: Q200
R13-R17 R19 R22 R23 R39 R52 = CMP-0086358-1: RES, 0, 0%, 0.25 W, AEC-Q200 Grade 0, 0603; Manufacturer: Rohm; Power_W: 250mW; SizeZ_mm: 1; SizeArea_mm2: 1.28; Value2: 0.25W; SizeAreaWB_mm2: 4.68; Value_Code: 0000; Value: 0; AEC Qualified: Y; AEC Category: Q200; SizeX_mm: 1.6; SizeY_mm: 0.8
R18 = CMP-0025925-5: RES, 47 k, 5%, 0.1 W, 0603; Manufacturer: Yageo; Power_W: 100mW; TempCo: 100 ppm/C; Value_Code: 47k0; Value: 47k; EIA_Code: E24; SizeX_mm: 1.6; SizeY_mm: 0.8; SizeZ_mm: 1; Value2: 0.1W; SizeArea_mm2: 1.28; AEC Qualified: N; VDC_V: 75V; AEC Category: Q200; SizeAreaWB_mm2: 4.68
R21 R24 R29 R67 R69-R72 = CMP-0025886-5: RES, 10 k, 5%, 0.1 W, 0603; Manufacturer: Yageo; Power_W: 100mW; TempCo: 100 ppm/C; Value_Code: 10k0; Value: 10k; EIA_Code: E24; SizeX_mm: 1.6; SizeY_mm: 0.8; SizeZ_mm: 1; Value2: 0.1W; SizeArea_mm2: 1.28; AEC Qualified: N; VDC_V: 75V; AEC Category: Q200; SizeAreaWB_mm2: 4.68
R25-R28 = CMP-2000-03817-1: Manufacturer: Vishay Dale
R57-R59 = CMP-0025757-4: RES, 22 k, 5%, 0.1 W, AEC-Q200 Grade 0, 0603; Manufacturer: Vishay-Dale; Power_W: 100mW; TempCo: 200 ppm/C; Value_Code: 22k0; Value: 22k; EIA_Code: E24; SizeX_mm: 1.6; SizeY_mm: 0.8; SizeZ_mm: 1; Value2: 0.1W; SizeArea_mm2: 1.28; AEC Qualified: Y; VDC_V: 75V; AEC Category: Q200; AEC Grade: 0
R61-R63 = CMP-0022438-1: RES, 47.0 k, 1%, 0.1 W, AEC-Q200 Grade 0, 0603; Manufacturer: Vishay-Dale; Power_W: 100mW; TempCo: 100 ppm/C; Value_Code: 47k0; U/M: EA; Value: 47.0k; Res_ohm: 47k; SizeX_mm: 1.6; SizeY_mm: 0.8; SizeZ_mm: 1; Value2: 0.1W; SizeArea_mm2: 1.28; AEC Qualified: Y; VDC_V: 75V; AEC Grade: 0; AEC Category: Q200
R64-R66 = CMP-0086261-1: RES, 100 k, 0.5%, 0.1 W, AEC-Q200 Grade 0, 0603; Manufacturer: Vishay-Dale; EIA_Code: E192; SizeZ_mm: 1; Power_W: 100mW; Value2: 0.1W; Value: 100k; SizeAreaWB_mm2: 4.68; AEC Qualified: Y; TempCo: 50 ppm/C; SizeArea_mm2: 1.28; AEC Category: Q200; SizeX_mm: 1.6; SizeY_mm: 0.8; AEC Grade: 0
R73 = CMP-0026935-3: RES, 47 k, 5%, 0.063 W, AEC-Q200 Grade 0, 0402; Manufacturer: Vishay-Dale; Power_W: 63mW; TempCo: 200 ppm/C; Value_Code: 47k0; Value: 47k; EIA_Code: E24; SizeX_mm: 1; SizeY_mm: 0.5; SizeZ_mm: 0.6; Value2: 0.063W; AEC Qualified: Y; VDC_V: 50V; AEC Category: Q200; AEC Grade: 0
S1 = CMP-0002134-3: Switch, Tactile, SPST-NO, 0.05A, 12V, SMT; Manufacturer: TE Connectivity; CurrentRating_mA: 50A; PositionCount: 1; SwitchFunction: Off-Mom
SH-J1-SH-J17 = CMP-0003761-2: Shunt, 2.54mm, Gold, Black; Manufacturer: Wurth Elektronik
TP1 TP2 TP5 TP6 = CMP-0055152-1: Test Point, Miniature, SMT; Manufacturer: Keystone; CNHeader: FALSE; Green_Lifecycle: Active; Green_REACh: Passed; CT: TRUE
TP3 = CMP-0003719-1: Testpoint; Manufacturer: Texas Instruments; CompType: Pad
TP4 TP7 TP8 TP10-TP17 = CMP-0055147-1: Test Point, Multipurpose, Red, TH; Manufacturer: Keystone; CNHeader: FALSE; Green_Lifecycle: Active; Green_REACh: Passed; ContactFinish: Silver; CT: TRUE
TP18 = CMP-0055147-2: Test Point, Multipurpose, Red, TH; Manufacturer: Keystone Electronics; CT: TRUE; ContactFinish: Silver; Green_Lifecycle: Active; CNHeader: FALSE; Green_REACh: Passed
U1 = CMP-0097829-1: Automotive H-Bridge Driver with Integrated Current Sense and Diagnostics; Manufacturer: Texas Instruments; TaMin_C: -40°C; Number Of Outputs: 2; Max Supply Voltage: 35V; Motor Type: Brushed; Min Supply Voltage: 4.5V; Nominal Supply Current: 3mA; Standoff Height: 0mm; TaMax_C: +125°C; AEC Qualified: Yes; TJmax_C: +150°C; Switching Frequency: 25kHz; SizeZ_mm: 1mm; AEC Grade: Grade 1
U2 = CMP-0070570-1: Ultra-Low Quiescent Current Voltage Regulator, 8-pin Narrow SOIC, Pb-Free; Manufacturer: Texas Instruments; PackageTopMarking: NSZXTT*LM903*6M-3; PowerWise: N; CompType: LDO IC
U3 = CMP-0365-00685-2: 16 MHz Mixed Signal Microcontroller with 16 KB Flash, 512 B SRAM and 24 GPIOs, -40 to 85 degC, 28-pin SOP (PW), Green (RoHS & no Sb/Br); Manufacturer: Texas Instruments; Timers - 16-bit: 2; Watchdog: Yes; GPIO: 24; SRAM(B): 512; Frequency(MHz): 16; USCI_B (I2C & SPI): 1; SubFamily: Value Line; ADC Channels: 8; ADC: 10-bit SAR
U4 = CMP-0076397-2: Zero Iq Reverse Polarity Protection Smart Diode Controller, DGK0008A (VSSOP-8); Manufacturer: Texas Instruments; SizeAreaWB_mm2: 23.6; SizeArea_mm2: 14.7; SizeZ_mm: 1.1; Green_REACh: Passed; SizeY_mm: 3; Green_Lifecycle: Active; CompType: IC; SizeX_mm: 4.9; AEC Category: Q200; AEC Qualified: Y
U8 = CMP-0077329-2: Automotive High-Voltage Ultra-Low IQ Low-Dropout Regulator/Fixed 5-V Output Voltage, DBV0005A (SOT-23-5); Manufacturer: Texas Instruments; SizeArea_mm2: 8.12; CompType: IC; SizeAreaWB_mm2: 14.82; SizeY_mm: 2.9; SizeZ_mm: 1.45; SizeX_mm: 2.8; AEC Category: Q200; AEC Qualified: Y

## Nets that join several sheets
3V3_MCU: ezFET (J7.10), MD074A (13 pins)
GND: ezFET (46 pins), MD074A (78 pins)
MCU_UARTRXD: ezFET (J7.8), MD074A (U3.3)
MCU_UARTTXD: ezFET (J7.6), MD074A (U3.4)
RST/SBWTDIO: ezFET (J7.4), MD074A (C52.1 J1.1 R73.1 U3.24)
TST/SBWTCK: ezFET (J7.2), MD074A (U3.25)

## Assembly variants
001: not fitted C3 C4 C5 C38 C39 C40 C41 C42 C43 C53 F2 FID1 FID2 FID3 R19 R25 R26 R27 R28 R29 R41 R67 R68 R70 R71 R72 TP18 U2 U8
002: not fitted C3 C4 C5 C38 C39 C40 C41 C42 C43 C53 F2 J10 J11 J12 J13 R13 R14 R15 R16 R17 R19 R21 R23 R24 R39 R41 R52 R53 R54 R55 R57 R58 R59 R61 R62 R63 R64 R65 R66 R67 R68 R70 R71 R72 SH-J2 SH-J13 SH-J14 SH-J16 TP18 U2 U8; alternate parts U1 -> CMP-0097831-1
003: not fitted C3 C4 C5 C38 C39 C42 C53 F2 J10 J11 J12 J13 R13 R14 R15 R16 R17 R21 R22 R23 R24 R39 R41 R52 R53 R54 R55 R57 R58 R59 R61 R62 R63 R64 R65 R66 R67 R68 R70 R71 R72 SH-J2 SH-J13 SH-J14 SH-J16 U2; alternate parts U1 -> CMP-0097830-1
